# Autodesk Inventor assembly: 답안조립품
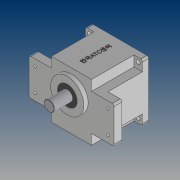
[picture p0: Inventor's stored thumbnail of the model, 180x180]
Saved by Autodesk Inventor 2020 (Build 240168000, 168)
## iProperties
Created: 2020-07
Part Number: 답안조립품
Document SubType Name: Assembly
Designer: PC312-
Author: PC312-
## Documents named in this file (10)
- C:\Users\PC312-\Desktop\700718V1009\답안조립품.iam
- C:\Users\PC312-\Desktop\700718V1009\본체.ipt
- C:\Users\PC312-\Desktop\700718V1009\커버.ipt
- C:\Users\PC312-\Desktop\700718V1009\베어링 608.ipt
- C:\Users\PC312-\Desktop\700718V1009\메인 축.ipt
- C:\Users\PC312-\Desktop\700718V1009\서브 축.ipt
- C:\Users\PC312-\Desktop\700718V1009\베어링 6003.ipt
- C:\Users\PC312-\Desktop\700718V1009\오일 실 8 22 7.ipt
- C:\Users\PC312-\Desktop\700718V1009\오일 실 17 32 8.ipt
- C:\Users\PC312-\Desktop\700718V1009\볼트 M4.ipt
